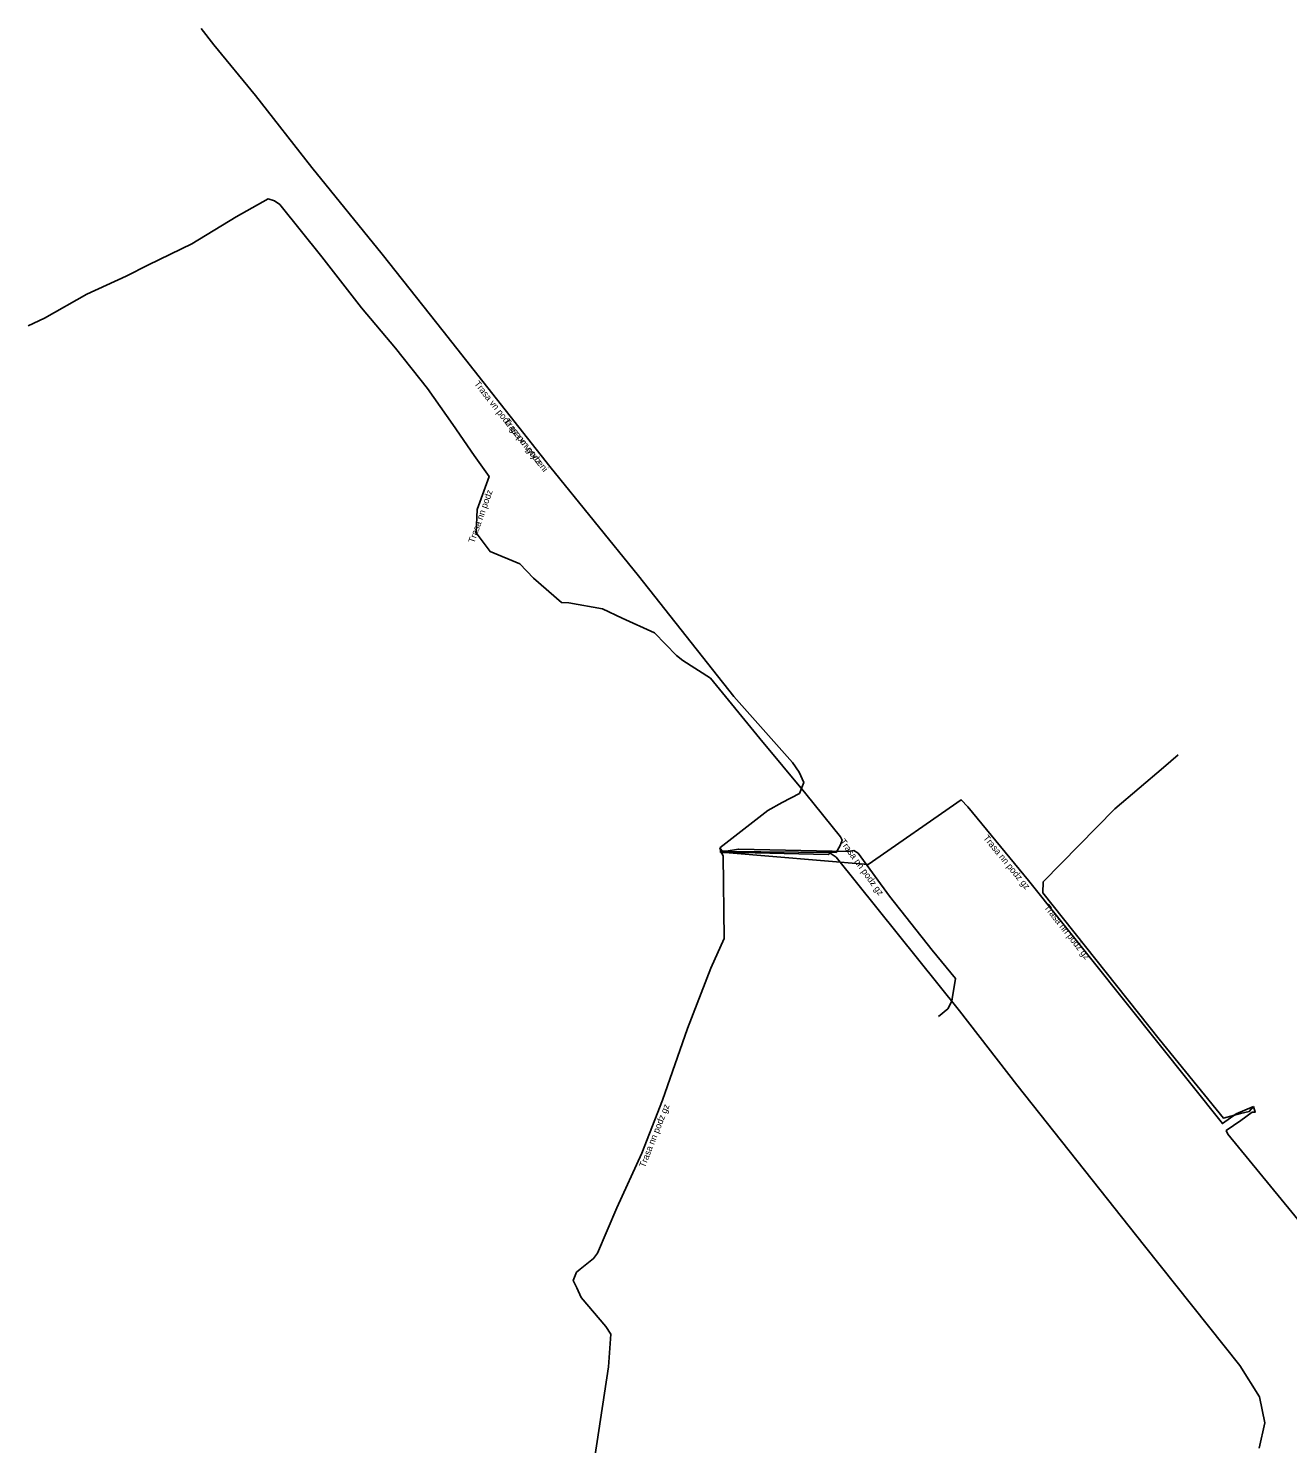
# Model space of a CAD drawing. Extents: x -570657 to -570353, y -1086847 to -1086630.
# Drawn here: x -570529.1 to -570432.4, y -1086738.1 to -1086629.5 of the extents above; entities that cross this region are included whole.
import ezdxf

# ---------------------------------------------------------------- set-up
doc = ezdxf.new("R2010")
doc.units = 0
for name, color, linetype in [('Popiskový text - Ostatní atributy Trasy', 7, 'Continuous'), ('Spojnice NN', 7, 'Continuous'), ('Spojnice VN', 7, 'Continuous')]:
    doc.layers.add(name, color=color, linetype=linetype)

msp = doc.modelspace()

# ---------------------------------------------------------------- linework, layer by layer
at = {"layer": 'Spojnice NN'}
for points in [[(-570475.97, -1086692.39), (-570475.73, -1086692.68), (-570467.05, -1086692.74), (-570466.73, -1086692.21), (-570466.6, -1086691.79), (-570466.71, -1086691.54), (-570469.38, -1086688.24), (-570472.9, -1086684), (-570476.7, -1086679.37), (-570478.82, -1086678.01), (-570479.29, -1086677.63), (-570480.98, -1086675.89), (-570483.48, -1086674.77), (-570484.99, -1086674.06), (-570487.57, -1086673.59), (-570488.12, -1086673.56), (-570490.28, -1086671.7), (-570491.33, -1086670.61), (-570493.61, -1086669.65), (-570494.67, -1086668.23), (-570494.59, -1086666.44), (-570493.69, -1086663.91), (-570494.83, -1086662.28), (-570496.46, -1086659.92), (-570498.42, -1086657.15), (-570500.86, -1086654.05), (-570503.47, -1086650.96), (-570506.53, -1086647.04), (-570509.75, -1086643.03), (-570510.16, -1086642.74), (-570510.63, -1086642.61), (-570511.06, -1086642.83), (-570513.1, -1086643.98), (-570516.49, -1086646.04), (-570519.83, -1086647.67), (-570521.54, -1086648.53), (-570524.56, -1086649.92), (-570527.82, -1086651.76), (-570529.05, -1086652.33)], [(-570440.79, -1086685.26), (-570441.93, -1086686.23), (-570445.66, -1086689.39), (-570451.17, -1086695), (-570451.19, -1086695.84), (-570442.26, -1086707.06), (-570437.32, -1086713.13), (-570436.01, -1086712.77), (-570435.35, -1086712.62), (-570435.01, -1086712.22)], [(-570435.01, -1086712.22), (-570436.36, -1086712.78), (-570437.4, -1086713.54), (-570452.28, -1086694.88), (-570456.94, -1086689.24), (-570457.46, -1086688.7), (-570464.6, -1086693.67), (-570475.58, -1086692.74), (-570475.92, -1086692.74), (-570475.92, -1086692.58)], [(-570484.51, -1086732.2), (-570484.35, -1086729.69), (-570484.73, -1086729.11), (-570486.62, -1086726.88), (-570486.96, -1086726.14), (-570487.23, -1086725.58), (-570486.97, -1086724.95), (-570486.7, -1086724.7), (-570485.67, -1086723.9), (-570485.37, -1086723.48), (-570483.88, -1086720.01), (-570481.97, -1086715.8), (-570480.37, -1086711.75), (-570478.46, -1086706.25), (-570476.67, -1086701.62), (-570475.65, -1086699.33), (-570475.72, -1086692.99), (-570475.88, -1086692.72), (-570475.97, -1086692.39)], [(-570459.2, -1086705.32), (-570458.48, -1086704.74), (-570458.18, -1086704.16), (-570458.15, -1086703.96), (-570457.9, -1086702.42), (-570459.69, -1086700.24), (-570462.95, -1086696.1), (-570465.36, -1086692.79), (-570465.68, -1086692.59), (-570466.15, -1086692.68), (-570474.55, -1086692.48), (-570475.49, -1086692.65), (-570475.8, -1086692.65), (-570475.97, -1086692.39)], [(-570434.59, -1086738.43), (-570434.15, -1086736.49), (-570434.57, -1086734.5), (-570436.06, -1086732.1), (-570443.38, -1086722.91), (-570453.17, -1086710.58), (-570457.59, -1086704.89), (-570467.04, -1086693.11), (-570467.52, -1086692.79), (-570467.66, -1086692.9), (-570475.52, -1086692.72), (-570475.76, -1086692.72), (-570475.97, -1086692.39)], [(-570425.54, -1086728.32), (-570436.99, -1086714.35), (-570437.11, -1086714.08), (-570435.99, -1086713.31), (-570435.12, -1086712.66), (-570434.89, -1086712.66), (-570435.01, -1086712.22)], [(-570484.51, -1086732.2), (-570485.87, -1086741.12), (-570485.99, -1086743.85), (-570486.36, -1086747.5), (-570486.31, -1086748.04), (-570483.96, -1086751.68), (-570483.28, -1086753.08), (-570482.8, -1086755.41), (-570482.84, -1086757.06), (-570483.07, -1086760.73), (-570483.08, -1086765.83), (-570483.19, -1086769.57), (-570482.47, -1086771.85), (-570482.28, -1086772.12), (-570480.84, -1086773.08), (-570480.36, -1086773.67), (-570478.38, -1086779.65), (-570475.97, -1086783.7), (-570473.08, -1086789.13), (-570471.06, -1086792.64), (-570468.63, -1086796.65), (-570468.8, -1086796.9), (-570468.95, -1086796.98), (-570469.36, -1086797.13)]]:
    msp.add_lwpolyline(points, dxfattribs=at)
at = {"layer": 'Spojnice VN'}
msp.add_lwpolyline([(-570475.97, -1086692.39), (-570472.28, -1086689.53), (-570471.2, -1086688.9), (-570469.86, -1086688.21), (-570469.53, -1086687.38), (-570469.89, -1086686.59), (-570470.39, -1086685.83), (-570474.89, -1086680.78), (-570482.21, -1086671.52), (-570489.03, -1086663.14), (-570497.22, -1086652.76), (-570501.9, -1086646.84), (-570507.28, -1086640.19), (-570511.61, -1086634.67), (-570514.82, -1086630.79), (-570515.79, -1086629.52)], dxfattribs=at)
msp.add_lwpolyline([(-570475.97, -1086692.39), (-570472.28, -1086689.53), (-570471.2, -1086688.9), (-570469.86, -1086688.21), (-570469.53, -1086687.38), (-570469.89, -1086686.59), (-570470.39, -1086685.83), (-570474.89, -1086680.78), (-570482.21, -1086671.52), (-570489.03, -1086663.14), (-570497.22, -1086652.76), (-570501.9, -1086646.84), (-570507.28, -1086640.19), (-570511.61, -1086634.67), (-570514.82, -1086630.79), (-570515.79, -1086629.52)], dxfattribs=at)

# ---------------------------------------------------------------- texts
at = {"layer": 'Popiskový text - Ostatní atributy Trasy'}
for s, rotation, p in [('Trasa vn podz gz po vytyceni', 308.2776, (-570494.86, -1086656.8)), ('Trasa vn podz', 308.2776, (-570492.58, -1086659.69)), ('Trasa nn podz', 70.4644, (-570494.83, -1086669.05)), ('Trasa nn podz gz', 306.0582, (-570466.8, -1086691.92)), ('Trasa nn podz gz', 309.5649, (-570455.79, -1086691.65)), ('Trasa nn podz gz', 308.4966, (-570451.12, -1086696.97)), ('Trasa nn podz gz', 68.3737, (-570481.73, -1086716.96))]:
    msp.add_text(s, height=0.5, rotation=rotation, dxfattribs=at).set_placement(p)

doc.saveas('drawing.dxf')
